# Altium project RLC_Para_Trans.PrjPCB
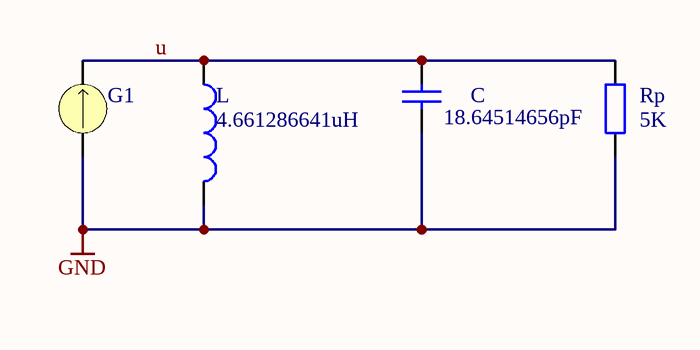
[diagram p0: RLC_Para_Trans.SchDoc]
1 sheet, 4 parts. Net scope: global (net labels, ports and power ports of the same name join across sheets).

## Sheet RLC_Para_Trans.SchDoc
size A4

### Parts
C  value 18.64514656pF  [RAD-0.3]  (hidden comment: Cap)
G1  ISRC  (value not drawn)
L  value 4.661286641uH  [0402-A]  (hidden comment: Inductor)
Rp  value 5K  [AXIAL-0.4]  (hidden comment: Res2)

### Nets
GND: C.1 G1.1 L.2 Rp.1
u: C.2 G1.2 L.1 Rp.2

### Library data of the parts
C = Cap: Capacitor
G1 = ISRC: Current Source; Note: PCB Footprint - Not required; Value: 1mA
L = Inductor: Code_IEC: 1005
Rp = Res2: Resistor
